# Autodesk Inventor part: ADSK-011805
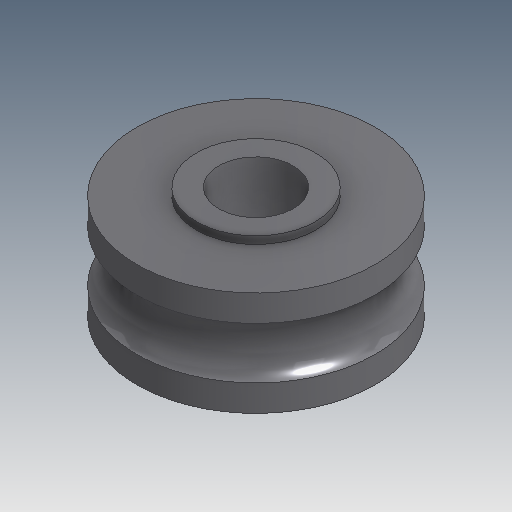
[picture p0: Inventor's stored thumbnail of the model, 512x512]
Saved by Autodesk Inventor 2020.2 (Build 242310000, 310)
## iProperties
Created: 2000-01
Part Number: ADSK-011805
Material: Acier doux
Description: LFR 50-5 KDD-4 ROLLER
Document SubType Name: Modeling
Designer: glanglot
Density: 7.86 g/cm^3
Appearance: Metal-Steel(Polish)
Mass: 9.30199 g
Surface Area: 8.84723 cm^2
Volume: 1.18346 cm^3
Control State: 0
Checked Out: False
Master: False
Shininess: 0.0
Length Units: 11269
Angle Units: 11279
Time Units: 11290
Mass Units: 11283
Length Display Precision: 3
Angle Display Precision: 2
Compacted: True
Dimensions: 8x16x16 mm
Mass: 0,009 kg
VLT_Material: Acier doux
Density: 0.0
Volumn: 0.0
Area: 0.0
PropertySet Name: Model Information
Author: glanglot
Revision Number: -
Title: LFR 50-5 KDD-4 ROLLER
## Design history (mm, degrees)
node "Revolution1" dims "d13" = 90 deg
node "Solide1"
node "Corps solides"
node "Corps surfaciques"
sketch "Sketch1"
  geometry: L1 (0, 20.248)-(0, -20.248); L2 (0, 0)-(55.28, 0); L3 (0, 4)-(4, 4); L4 (0, -4)-(4, -4); L5 (2.5, 4)-(2.5, -4); L6 (4, 4)-(4, -4); L7 (4, 3.5)-(8, 3.5); L8 (4, -3.5)-(8, -3.5); L9 (8, -1.732)-(8, -3.5); L10 (8, 1.732)-(8, 3.5); L11 (8, 1.732)-(8, -1.732); A1 r 2 centre (9, 0) between (8, -1.732) and (8, 1.732); 1 further point
  constraints: 22 end point, 7 point on line, 6 parallel, 2 collinear, 2 point on circle, 1 centre point, 1 coincident, 1 midpoint, 1 perpendicular, 1 vertical
  dimensions: "d4" = 4 distance between parallel lines of L4 L2 (= 0.5 x B); "d5" = 4 distance between parallel lines of L3 L2 (= 0.5 x B); "d7" = 2.5 distance between parallel lines of L5 L1 (= 0.5 x d); "d8" = 4 distance between parallel lines of L6 L1 (computed from d); "d9" = 3.5 distance between parallel lines of L7 L2 (= 0.5 x C); "d10" = 3.5 distance between parallel lines of L8 L2 (= 0.5 x C); "d11" = 4 diameter of A1 (= dLW); "d12" = 9 distance from line of A1.centre L1 (= A4)
other parameters: "A4" = 9 [user parameter; used in 1 equation term], "r" = 0.2 [user parameter], "d" = 5 [user parameter; used in 2 equation terms], "D" = 16 [user parameter; used in 1 equation term], "C" = 7 [user parameter; used in 4 equation terms], "B" = 8 [user parameter; used in 2 equation terms], "dLW" = 4 [user parameter; used in 1 equation term], "d0" = 3.5 (= 0.5 x C), "d1" = 3.5 (= 0.5 x C), "d14" = 8 (= 0.5 x D)
